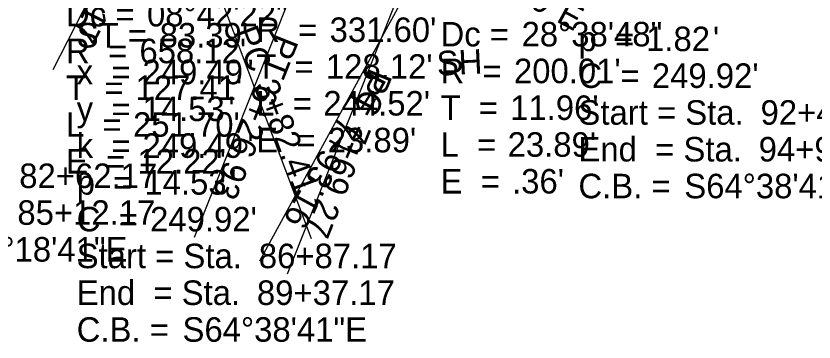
# Model space of a CAD drawing. Extents: x 2000474 to 2003418, y 251807 to 253801.
# Drawn here: x 2001296 to 2002433, y 252227 to 252692 of the extents above; entities that cross this region are included whole.
import ezdxf

# ---------------------------------------------------------------- set-up
doc = ezdxf.new("R2010")
doc.units = 0
for name, color, linetype in [('BD_X_Building', 7, 'Continuous'), ('DR_X_Flow_Arrow', 7, 'Continuous'), ('DV_X_Township_Line', 7, 'Continuous'), ('GE_P_Alignment_100_Stations', 7, 'Continuous'), ('RW_P_Text', 7, 'Continuous'), ('RW_X_CL_100_Stations', 7, 'Continuous'), ('RW_X_CL_500_Stations', 7, 'Continuous'), ('SC_Scratch1', 7, 'Continuous'), ('SC_Scratch3', 7, 'Continuous'), ('SC_Scratch5', 7, 'Continuous'), ('SC_Shading1', 7, 'Continuous'), ('TX_X_50', 7, 'Continuous')]:
    doc.layers.add(name, color=color, linetype=linetype)

msp = doc.modelspace()

# ---------------------------------------------------------------- linework, layer by layer
at = {"layer": 'DR_X_Flow_Arrow'}
for p, q in [((2001518.9, 252901.1), (2001716.5, 252374.4)), ((2001757.9, 252898.7), (2001550.1, 252376)), ((2001890.2, 252846.1), (2001682.4, 252323.4)), ((2001911.8, 252836), (2001643.2, 252341.8))]:
    msp.add_line(p, q, dxfattribs=at)
at = {"layer": 'RW_P_Text'}
for p, q in [((2001518.9, 252901.1), (2001716.5, 252374.4)), ((2001757.9, 252898.7), (2001550.1, 252376)), ((2001890.2, 252846.1), (2001682.4, 252323.4)), ((2001911.8, 252836), (2001643.2, 252341.8))]:
    msp.add_line(p, q, dxfattribs=at)
at = {"layer": 'RW_X_CL_100_Stations'}
for p, q in [((2001604.2, 253116.2), (2001348.7, 252615.1)), ((2001518.9, 252901.1), (2001716.5, 252374.4)), ((2001757.9, 252898.7), (2001550.1, 252376)), ((2001890.2, 252846.1), (2001682.4, 252323.4)), ((2001911.8, 252836), (2001643.2, 252341.8))]:
    msp.add_line(p, q, dxfattribs=at)
at = {"layer": 'SC_Scratch3'}
msp.add_line((2001604.2, 253116.2), (2001348.7, 252615.1), dxfattribs=at)
at = {"layer": 'TX_X_50'}
msp.add_line((2001604.2, 253116.2), (2001348.7, 252615.1), dxfattribs=at)

# ---------------------------------------------------------------- texts
at = {"layer": 'BD_X_Building'}
msp.add_text('S61°28\'29"E', height=35, rotation=331.4747, dxfattribs=at).set_placement((2001860.9, 252795.4))
for s, p in [('Dc = ', (2001367.4, 252677.1)), ('08°42\'22"', (2001482.8, 252677.1)), ('R  = ', (2001638.4, 252654.9)), ("331.60'", (2001743, 252654.9)), ('Dc = ', (2001901, 252648.6)), ('28°38\'48"', (2002016.5, 252648.6)), ('R  = ', (2001367.4, 252624.6)), ("658.12'", (2001472, 252624.6)), ('T  = ', (2001638.4, 252602.4)), ("128.12'", (2001737.6, 252602.4)), ('R  = ', (2001901, 252596.1)), ("200.01'", (2002005.6, 252596.1)), ('T  = ', (2001367.4, 252572.1)), ("127.41'", (2001466.5, 252572.1)), ('L  = ', (2001638.4, 252549.9)), ("244.52'", (2001734, 252549.9)), ('T  = ', (2001901, 252543.6)), ("11.96'", (2002000.2, 252543.6)), ('L  = ', (2001367.4, 252519.6)), ("251.70'", (2001462.9, 252519.6)), ('E  = ', (2001638.4, 252497.4)), ("23.89'", (2001740.3, 252497.4)), ('L  = ', (2001901, 252491.1)), ("23.89'", (2001996.6, 252491.1)), ('E  = ', (2001367.4, 252467.1)), ("12.22'", (2001469.3, 252467.1)), ('E  = ', (2001901, 252438.6)), (".36'", (2002002.9, 252438.6))]:
    msp.add_text(s, height=35, dxfattribs=at).set_placement(p)
at = {"layer": 'DR_X_Flow_Arrow'}
for s, rotation, p in [('PC', 290.5675, (2001606.3, 252669.9)), ('PT', 248.3173, (2001666.9, 252668.1)), ('PT', 241.4747, (2001794.1, 252618.1)), ('PC', 248.3173, (2001800.5, 252619)), ('6+26.93', 248.3173, (2001638.8, 252597.5)), ('3+82.41', 290.5675, (2001634.9, 252593.6)), ('7+93.16', 241.4747, (2001757.7, 252551.3)), ('7+69.27', 248.3173, (2001770.4, 252543.2))]:
    msp.add_text(s, height=35, rotation=rotation, dxfattribs=at).set_placement(p)
at = {"layer": 'DV_X_Township_Line'}
msp.add_text('S61°28\'29"E', height=35, rotation=331.4747, dxfattribs=at).set_placement((2001860.9, 252795.4))
for s, p in [('Dc = ', (2001367.4, 252677.1)), ('08°42\'22"', (2001482.8, 252677.1)), ('R  = ', (2001638.4, 252654.9)), ("331.60'", (2001743, 252654.9)), ('Dc = ', (2001901, 252648.6)), ('28°38\'48"', (2002016.5, 252648.6)), ('R  = ', (2001367.4, 252624.6)), ("658.12'", (2001472, 252624.6)), ('T  = ', (2001638.4, 252602.4)), ("128.12'", (2001737.6, 252602.4)), ('R  = ', (2001901, 252596.1)), ("200.01'", (2002005.6, 252596.1)), ('T  = ', (2001367.4, 252572.1)), ("127.41'", (2001466.5, 252572.1)), ('L  = ', (2001638.4, 252549.9)), ("244.52'", (2001734, 252549.9)), ('T  = ', (2001901, 252543.6)), ("11.96'", (2002000.2, 252543.6)), ('L  = ', (2001367.4, 252519.6)), ("251.70'", (2001462.9, 252519.6)), ('E  = ', (2001638.4, 252497.4)), ("23.89'", (2001740.3, 252497.4)), ('L  = ', (2001901, 252491.1)), ("23.89'", (2001996.6, 252491.1)), ('E  = ', (2001367.4, 252467.1)), ("12.22'", (2001469.3, 252467.1)), ('E  = ', (2001901, 252438.6)), (".36'", (2002002.9, 252438.6))]:
    msp.add_text(s, height=35, dxfattribs=at).set_placement(p)
at = {"layer": 'GE_P_Alignment_100_Stations'}
msp.add_text('S61°28\'29"E', height=35, rotation=331.4747, dxfattribs=at).set_placement((2001860.9, 252795.4))
for s, p in [('Dc = ', (2001367.4, 252677.1)), ('08°42\'22"', (2001482.8, 252677.1)), ('R  = ', (2001638.4, 252654.9)), ("331.60'", (2001743, 252654.9)), ('Dc = ', (2001901, 252648.6)), ('28°38\'48"', (2002016.5, 252648.6)), ('R  = ', (2001367.4, 252624.6)), ("658.12'", (2001472, 252624.6)), ('T  = ', (2001638.4, 252602.4)), ("128.12'", (2001737.6, 252602.4)), ('R  = ', (2001901, 252596.1)), ("200.01'", (2002005.6, 252596.1)), ('T  = ', (2001367.4, 252572.1)), ("127.41'", (2001466.5, 252572.1)), ('L  = ', (2001638.4, 252549.9)), ("244.52'", (2001734, 252549.9)), ('T  = ', (2001901, 252543.6)), ("11.96'", (2002000.2, 252543.6)), ('L  = ', (2001367.4, 252519.6)), ("251.70'", (2001462.9, 252519.6)), ('E  = ', (2001638.4, 252497.4)), ("23.89'", (2001740.3, 252497.4)), ('L  = ', (2001901, 252491.1)), ("23.89'", (2001996.6, 252491.1)), ('E  = ', (2001367.4, 252467.1)), ("12.22'", (2001469.3, 252467.1)), ('E  = ', (2001901, 252438.6)), (".36'", (2002002.9, 252438.6))]:
    msp.add_text(s, height=35, dxfattribs=at).set_placement(p)
at = {"layer": 'RW_P_Text'}
for s, rotation, p in [('PC', 290.5675, (2001606.3, 252669.9)), ('PT', 248.3173, (2001666.9, 252668.1)), ('PT', 241.4747, (2001794.1, 252618.1)), ('PC', 248.3173, (2001800.5, 252619)), ('6+26.93', 248.3173, (2001638.8, 252597.5)), ('3+82.41', 290.5675, (2001634.9, 252593.6)), ('7+93.16', 241.4747, (2001757.7, 252551.3)), ('7+69.27', 248.3173, (2001770.4, 252543.2))]:
    msp.add_text(s, height=35, rotation=rotation, dxfattribs=at).set_placement(p)
at = {"layer": 'RW_X_CL_100_Stations'}
for s, rotation, p in [('89+37.17', 242.9781, (2001464.2, 252840.2)), ('PC', 290.5675, (2001606.3, 252669.9)), ('PT', 248.3173, (2001666.9, 252668.1)), ('PT', 241.4747, (2001794.1, 252618.1)), ('PC', 248.3173, (2001800.5, 252619)), ('6+26.93', 248.3173, (2001638.8, 252597.5)), ('3+82.41', 290.5675, (2001634.9, 252593.6)), ('7+93.16', 241.4747, (2001757.7, 252551.3)), ('7+69.27', 248.3173, (2001770.4, 252543.2))]:
    msp.add_text(s, height=35, rotation=rotation, dxfattribs=at).set_placement(p)
at = {"layer": 'RW_X_CL_500_Stations'}
for s, p in [('ST = ', (2001382.6, 252647)), ("83.39'", (2001500.8, 252647)), ('1.82', (2002193.9, 252641.8)), ("'", (2002289.1, 252641.8)), ('p  = ', (2002097.5, 252641.8)), ('249.49', (2001476.4, 252594.5)), ("'", (2001625.9, 252594.5)), ('C  = ', (2002097.5, 252589.3)), ("249.92'", (2002202.1, 252589.3)), ('x  = ', (2001382.6, 252594.5)), ('y  = ', (2001382.6, 252542)), ('14.53', (2001476.4, 252542)), ("'", (2001598.7, 252542)), ('Start = Sta. ', (2002097.5, 252536.8)), ('92+42.07', (2002357, 252536.8)), ('k  = ', (2001382.6, 252489.5)), ('249.49', (2001476.4, 252489.5)), ("'", (2001625.9, 252489.5)), ('End  = Sta. ', (2002097.5, 252484.3)), ('94+92.07', (2002354.3, 252484.3)), ('82+62.17', (2001300.8, 252446.4)), ('14.53', (2001479.1, 252437)), ("'", (2001601.4, 252437)), ('C.B. = ', (2002097.5, 252431.8)), ('S64°38\'41"E', (2002248.3, 252431.8)), ('p  = ', (2001382.6, 252437)), ('85+12.17', (2001298.1, 252393.9)), ('C  = ', (2001382.6, 252384.5)), ("249.92'", (2001487.2, 252384.5)), ('S78°18\'41"E', (2001192.1, 252341.4)), ('Start = Sta. ', (2001382.6, 252332)), ('86+87.17', (2001642.1, 252332)), ('End  = Sta. ', (2001382.6, 252279.5)), ('89+37.17', (2001639.4, 252279.5)), ('C.B. = ', (2001382.6, 252227)), ('S64°38\'41"E', (2001533.4, 252227))]:
    msp.add_text(s, height=35, dxfattribs=at).set_placement(p)
at = {"layer": 'SC_Scratch1'}
msp.add_text('SH', height=35, rotation=2.8513, dxfattribs=at).set_placement((2001896.4, 252606.7))
at = {"layer": 'SC_Scratch3'}
msp.add_text('89+37.17', height=35, rotation=242.9781, dxfattribs=at).set_placement((2001464.2, 252840.2))
at = {"layer": 'SC_Scratch5'}
for s, p in [('ST = ', (2001382.6, 252647)), ("83.39'", (2001500.8, 252647)), ('1.82', (2002193.9, 252641.8)), ("'", (2002289.1, 252641.8)), ('p  = ', (2002097.5, 252641.8)), ('249.49', (2001476.4, 252594.5)), ("'", (2001625.9, 252594.5)), ('C  = ', (2002097.5, 252589.3)), ("249.92'", (2002202.1, 252589.3)), ('x  = ', (2001382.6, 252594.5)), ('y  = ', (2001382.6, 252542)), ('14.53', (2001476.4, 252542)), ("'", (2001598.7, 252542)), ('Start = Sta. ', (2002097.5, 252536.8)), ('92+42.07', (2002357, 252536.8)), ('k  = ', (2001382.6, 252489.5)), ('249.49', (2001476.4, 252489.5)), ("'", (2001625.9, 252489.5)), ('End  = Sta. ', (2002097.5, 252484.3)), ('94+92.07', (2002354.3, 252484.3)), ('82+62.17', (2001300.8, 252446.4)), ('14.53', (2001479.1, 252437)), ("'", (2001601.4, 252437)), ('C.B. = ', (2002097.5, 252431.8)), ('S64°38\'41"E', (2002248.3, 252431.8)), ('p  = ', (2001382.6, 252437)), ('85+12.17', (2001298.1, 252393.9)), ('C  = ', (2001382.6, 252384.5)), ("249.92'", (2001487.2, 252384.5)), ('S78°18\'41"E', (2001192.1, 252341.4)), ('Start = Sta. ', (2001382.6, 252332)), ('86+87.17', (2001642.1, 252332)), ('End  = Sta. ', (2001382.6, 252279.5)), ('89+37.17', (2001639.4, 252279.5)), ('C.B. = ', (2001382.6, 252227)), ('S64°38\'41"E', (2001533.4, 252227))]:
    msp.add_text(s, height=35, dxfattribs=at).set_placement(p)
at = {"layer": 'SC_Shading1'}
for s, p in [('ST = ', (2001382.6, 252647)), ("83.39'", (2001500.8, 252647)), ('1.82', (2002193.9, 252641.8)), ("'", (2002289.1, 252641.8)), ('p  = ', (2002097.5, 252641.8)), ('249.49', (2001476.4, 252594.5)), ("'", (2001625.9, 252594.5)), ('C  = ', (2002097.5, 252589.3)), ("249.92'", (2002202.1, 252589.3)), ('x  = ', (2001382.6, 252594.5)), ('y  = ', (2001382.6, 252542)), ('14.53', (2001476.4, 252542)), ("'", (2001598.7, 252542)), ('Start = Sta. ', (2002097.5, 252536.8)), ('92+42.07', (2002357, 252536.8)), ('k  = ', (2001382.6, 252489.5)), ('249.49', (2001476.4, 252489.5)), ("'", (2001625.9, 252489.5)), ('End  = Sta. ', (2002097.5, 252484.3)), ('94+92.07', (2002354.3, 252484.3)), ('82+62.17', (2001300.8, 252446.4)), ('14.53', (2001479.1, 252437)), ("'", (2001601.4, 252437)), ('C.B. = ', (2002097.5, 252431.8)), ('S64°38\'41"E', (2002248.3, 252431.8)), ('p  = ', (2001382.6, 252437)), ('85+12.17', (2001298.1, 252393.9)), ('C  = ', (2001382.6, 252384.5)), ("249.92'", (2001487.2, 252384.5)), ('S78°18\'41"E', (2001192.1, 252341.4)), ('Start = Sta. ', (2001382.6, 252332)), ('86+87.17', (2001642.1, 252332)), ('End  = Sta. ', (2001382.6, 252279.5)), ('89+37.17', (2001639.4, 252279.5)), ('C.B. = ', (2001382.6, 252227)), ('S64°38\'41"E', (2001533.4, 252227))]:
    msp.add_text(s, height=35, dxfattribs=at).set_placement(p)
at = {"layer": 'TX_X_50'}
msp.add_text('89+37.17', height=35, rotation=242.9781, dxfattribs=at).set_placement((2001464.2, 252840.2))

doc.saveas('drawing.dxf')
